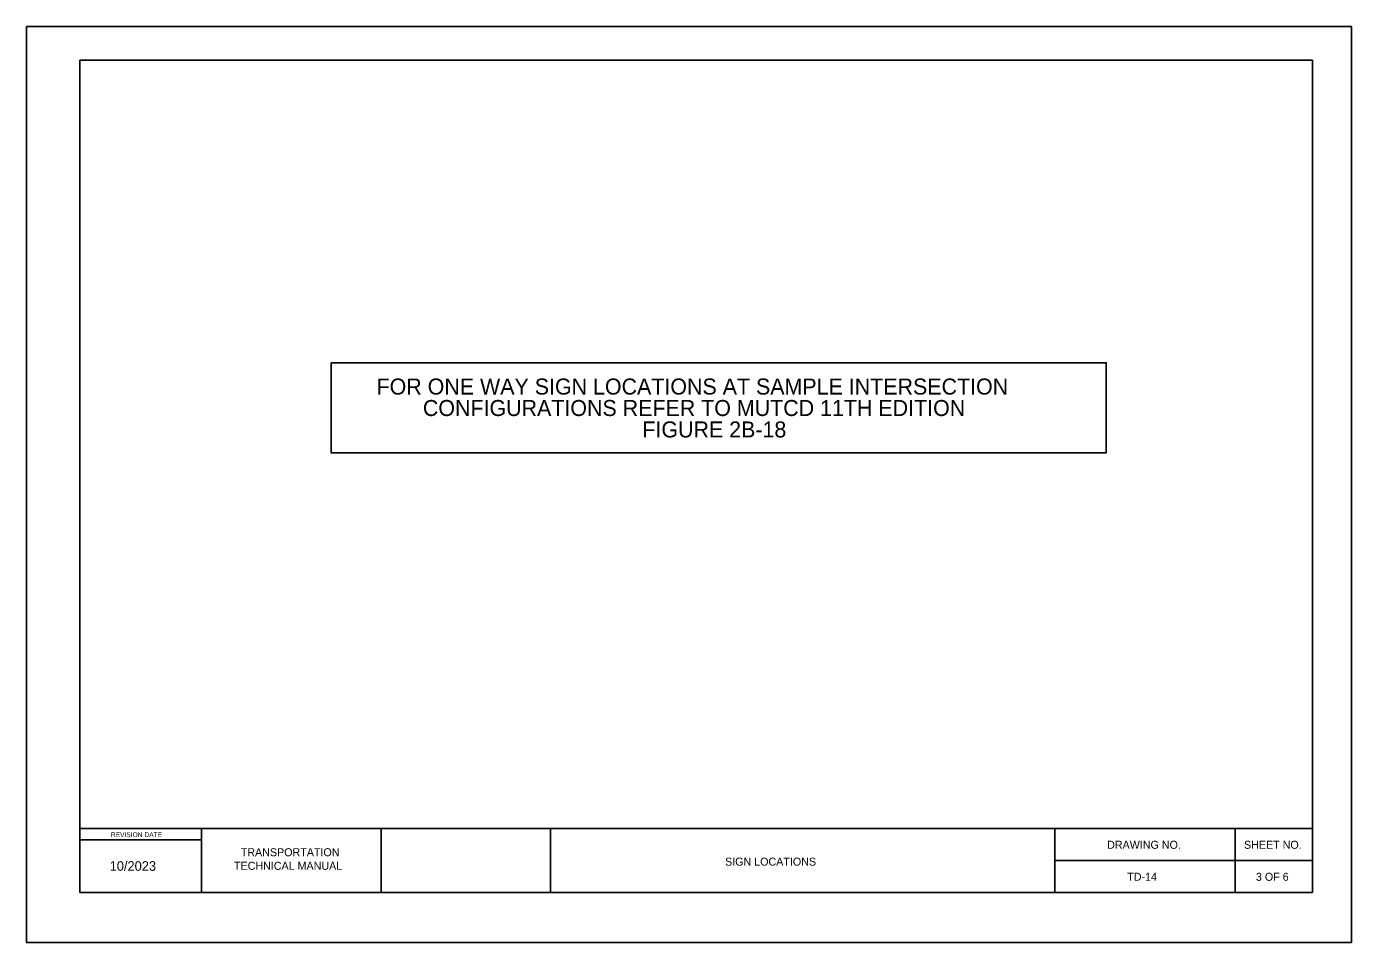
# Model space of a CAD drawing. Extents: x -14.6 to 39.7, y -12.4 to 25.1.
import ezdxf

# ---------------------------------------------------------------- set-up
doc = ezdxf.new("R2010")
doc.units = 0
for name, color, linetype in [('Default', 7, 'Continuous'), ('NonPlottingEle_dp', 7, 'Continuous'), ('SheetBorder_dp', 7, 'Continuous'), ('SheetLines_dp', 7, 'Continuous'), ('TextMinor', 7, 'Continuous')]:
    doc.layers.add(name, color=color, linetype=linetype)

msp = doc.modelspace()

# ---------------------------------------------------------------- linework, layer by layer
at = {"layer": 'Default'}
msp.add_lwpolyline([(-2.085, 11.359), (29.691, 11.359), (29.691, 7.669), (-2.085, 7.669)], close=True, dxfattribs=at)
at = {"layer": 'NonPlottingEle_dp'}
msp.add_lwpolyline([(38.12, 25.141), (-14.569, 25.141), (-14.569, -12.409), (39.74, -12.409), (39.74, 25.141)], close=True, dxfattribs=at)
at = {"layer": 'SheetBorder_dp'}
for p, q in [((-12.382, 23.76), (-12.382, -10.361)), ((-12.382, 23.76), (38.143, 23.76)), ((38.143, 23.76), (38.143, -10.361)), ((-12.382, -7.741), (38.143, -7.741)), ((-12.382, -10.361), (38.143, -10.361))]:
    msp.add_line(p, q, dxfattribs=at)
at = {"layer": 'SheetLines_dp'}
for p, q in [((-7.394, -7.736), (-7.394, -10.361)), ((-0.027, -7.736), (-0.027, -10.361)), ((6.912, -7.741), (6.912, -10.361)), ((27.582, -10.361), (27.582, -7.736)), ((34.972, -10.361), (34.972, -7.736)), ((-12.382, -8.196), (-7.394, -8.196)), ((27.582, -9.049), (38.143, -9.049))]:
    msp.add_line(p, q, dxfattribs=at)

# ---------------------------------------------------------------- texts
at = {"layer": 'TextMinor'}
for s, height, p in [('FOR ONE WAY SIGN LOCATIONS AT SAMPLE INTERSECTION ', 0.65617, (-0.221, 10.054)), ('CONFIGURATIONS REFER TO MUTCD 11TH EDITION ', 0.65617, (1.678, 9.174)), ('FIGURE 2B-18', 0.65617, (10.674, 8.295)), ('REVISION DATE', 0.19685, (-11.112, -8.089)), ('TRANSPORTATION', 0.32808, (-5.786, -8.873)), ('DRAWING NO.', 0.32808, (29.724, -8.567)), ('SHEET NO.', 0.3281, (35.335, -8.567)), ('10/2023', 0.3937, (-11.162, -9.47)), ('TECHNICAL MANUAL', 0.32808, (-6.066, -9.43)), ('SIGN LOCATIONS', 0.32808, (14.064, -9.259)), ('TD-14', 0.3281, (30.548, -9.879)), ('3 OF 6 ', 0.3281, (35.824, -9.879))]:
    msp.add_text(s, height=height, dxfattribs=at).set_placement(p)

doc.saveas('drawing.dxf')
